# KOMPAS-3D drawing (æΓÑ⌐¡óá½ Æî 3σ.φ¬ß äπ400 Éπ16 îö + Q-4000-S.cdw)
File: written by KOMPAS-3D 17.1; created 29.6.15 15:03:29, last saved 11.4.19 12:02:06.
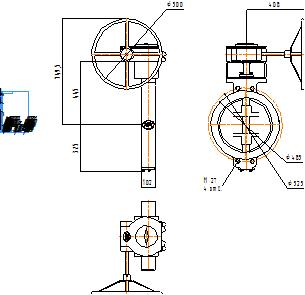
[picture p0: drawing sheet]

Sheet 1: A4, portrait

Title block, sheet 1: mass: 139; sheets: 1; organisation: ООО "Торговый дом АДЛ"; sheet format: A4; stored path: \\adlc.lan\data\АДЛ_ПКД\3D-модели\ADL production\Дисковые поворотные затворы СТЕЙНВАЛ\Трехэксцентриковый\Стейнвал м-ф\С редуктором\KOMPAS 2D\Стейнвал ТМ 3х.экс Ду400 Ру16 МФ + Q-4000-S.cdw

Views: Вид 4, Проекционный вид 6
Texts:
  Klimkovich
  ADL
Dimensions and other numbers on the sheet: 325; 102; 445; 749,5; 500; 1:1; 1; 139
